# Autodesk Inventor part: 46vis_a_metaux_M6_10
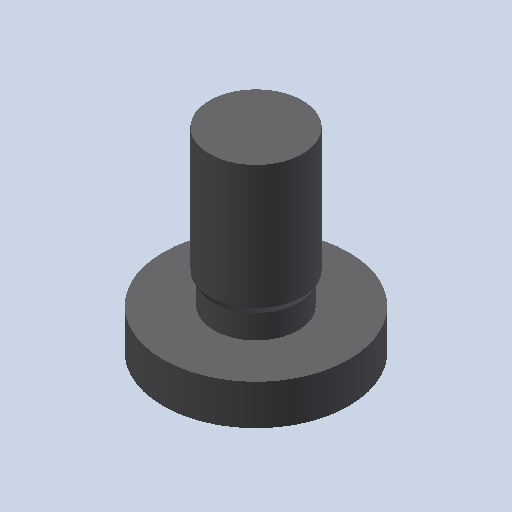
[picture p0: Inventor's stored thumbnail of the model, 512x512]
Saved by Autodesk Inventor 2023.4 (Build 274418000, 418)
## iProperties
Created: 2011-01
Part Number: 46vis_a_metaux_M6_10
Document SubType Name: Modeling
Designer: eric
Density: 1 g/cm^3
Mass: 0.629927 g
Surface Area: 5.79103 cm^2
Volume: 0.629927 cm^3
Material: Générique
Appearance: Red
Author: eric
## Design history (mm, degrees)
feature "Base1"
node "Corps solides"
node "Corps surfaciques"
node "Solide1"
